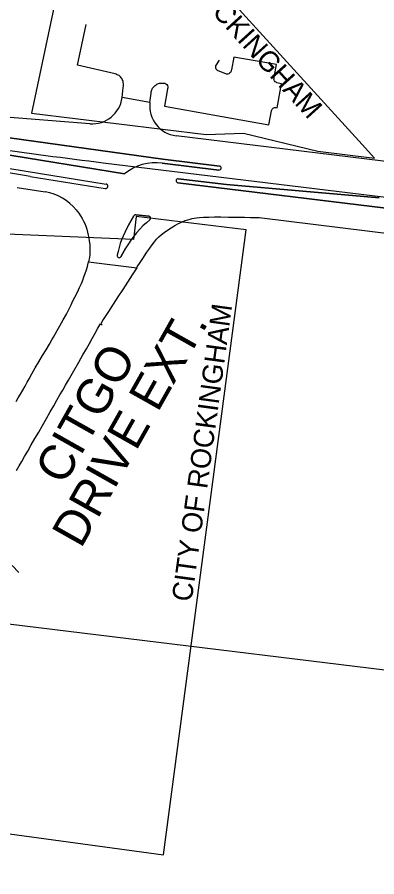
# Model space of a CAD drawing. Extents: x 1756435 to 1766932, y 416863 to 426859.
# Drawn here: x 1763464 to 1763823, y 423038 to 423897 of the extents above; entities that cross this region are included whole.
import ezdxf

# ---------------------------------------------------------------- set-up
doc = ezdxf.new("R2010")
doc.units = 0
for name, color, linetype in [('Exist Boundary City Limits', 7, 'Continuous'), ('Exist Roads EOP', 7, 'Continuous'), ('Exist Roads EOP Other', 7, 'Continuous'), ('Prop Horizontal Alignment', 7, 'Continuous'), ('Prop Lane Lines', 7, 'Continuous'), ('Prop Shade Light', 7, 'Continuous'), ('Prop Shade Medium', 7, 'Continuous'), ('Sheet Data Field CELL', 7, 'Continuous'), ('Sheet Plan CELL', 7, 'Continuous')]:
    doc.layers.add(name, color=color, linetype=linetype)

msp = doc.modelspace()

# ---------------------------------------------------------------- linework, layer by layer
at = {"layer": 'Exist Boundary City Limits'}
for points in [[(1763808.64, 423769.81), (1763627.49, 423968.89), (1763535.51, 424069.97), (1763478.5, 423801.07), (1763652.88, 423779.73), (1763689.95, 423781.03), (1763764.16, 423763.14), (1763820.91, 423756.2), (1763808.64, 423769.81), (1763808.64, 423769.81)], [(1762880.67, 423159.66), (1763610.22, 423060.06), (1763692.83, 423684.46), (1763583.09, 423697.89), (1763580.16, 423674.65), (1763153.55, 423692.65), (1763091.03, 423571.76), (1763039.83, 423506.29), (1762974.04, 423447.46), (1762934.14, 423389.22), (1762925.42, 423350.93), (1762898.59, 423287.45), (1762877.48, 423297.28), (1762869.53, 423205.69), (1762867.5, 423196.1), (1762876.5, 423188.61), (1762880.67, 423159.66)]]:
    msp.add_lwpolyline(points, dxfattribs=at)
at = {"layer": 'Exist Roads EOP'}
for points in [[(1763518.12, 423611.9), (1763518.87, 423611.48), (1763521.84, 423617.05), (1763524.4, 423622.2), (1763526.54, 423626.81), (1763528.25, 423630.76), (1763529.65, 423634.27), (1763530.88, 423637.53), (1763532.05, 423640.81), (1763533.26, 423644.38), (1763534.37, 423647.95), (1763535.22, 423651.25), (1763535.49, 423652.55)], [(1763583.56, 423646.67), (1763578.84, 423639.37), (1763574.19, 423632.11), (1763569.53, 423624.86), (1763564.79, 423617.53), (1763560.03, 423610.24), (1763555.25, 423602.9), (1763550.2, 423594.91), (1763547.56, 423590.63), (1763549.05, 423589.64)], [(1763463.21, 423513.11), (1763465.23, 423516.58), (1763467.46, 423520.39), (1763469.74, 423524.36), (1763472.02, 423528.41), (1763474.11, 423532.15), (1763476.13, 423535.72), (1763478.85, 423540.48), (1763482.31, 423546.49), (1763485.91, 423552.68), (1763489.54, 423558.84), (1763493.07, 423564.77), (1763496.37, 423570.27), (1763498.81, 423574.44), (1763500.42, 423577.35), (1763502.11, 423580.37), (1763504.1, 423583.87), (1763506.78, 423588.64), (1763510.1, 423594.57), (1763513.33, 423600.28), (1763516.23, 423605.45), (1763518.17, 423609.5), (1763518.75, 423611.08)], [(1763463.65, 423443.97), (1763466.31, 423448.61), (1763468.84, 423453.01), (1763471.68, 423457.98), (1763474.82, 423463.49), (1763478.29, 423469.56), (1763481.94, 423475.97), (1763485.68, 423482.51), (1763489.49, 423489.17), (1763493.37, 423495.96), (1763497.16, 423502.57), (1763500.66, 423508.7), (1763503.9, 423514.34), (1763506.85, 423519.51), (1763509.66, 423524.42), (1763512.47, 423529.32), (1763515.27, 423534.21), (1763518.07, 423539.08), (1763520.77, 423543.79), (1763525.61, 423552.25), (1763529.72, 423559.49), (1763533.28, 423565.72), (1763536.34, 423571.05), (1763539.09, 423575.94), (1763541.68, 423580.66), (1763544.81, 423586.34), (1763546.62, 423589.61), (1763547.37, 423590.42)], [(1763465.98, 423342.28), (1763459.18, 423349.28)]]:
    msp.add_lwpolyline(points, dxfattribs=at)
at = {"layer": 'Exist Roads EOP Other'}
for p, q in [((1763662.41, 423848.24), (1763666.03, 423853.79)), ((1763673.24, 423840.06), (1763664.15, 423843.46)), ((1763568.87, 423816.5), (1763570.15, 423826.52)), ((1763596.72, 423811.7), (1763597.84, 423821.11))]:
    msp.add_line(p, q, dxfattribs=at)
for points in [[(1763561.98, 423840.15), (1763524.39, 423848.86), (1763533, 423889.67)], [(1763720.86, 423836.83), (1763722.97, 423849.59), (1763680.54, 423856.96), (1763678.14, 423844.19)], [(1763722.21, 423806.74), (1763723.78, 423806.46), (1763727.88, 423830.19), (1763723.54, 423831.42)], [(1763614.32, 423825.15), (1763611.16, 423808.13), (1763659.36, 423799.42), (1763715.44, 423789.39), (1763718.07, 423803.32)]]:
    msp.add_lwpolyline(points, dxfattribs=at)
for points in [[(1763664.15, 423843.46), (1763662.89, 423844.88), (1763662.42, 423846.99), (1763662.41, 423848.24)], [(1763678.14, 423844.19), (1763676.97, 423841.63), (1763675.45, 423840.36), (1763673.24, 423840.06)], [(1763570.15, 423826.52), (1763570.16, 423831.68), (1763568.65, 423835.5), (1763565.88, 423838.45), (1763561.98, 423840.15)], [(1763723.54, 423831.42), (1763721.82, 423832.29), (1763720.51, 423834.47), (1763720.86, 423836.83)], [(1763597.84, 423821.11), (1763598.9, 423825.09), (1763601.33, 423828.06), (1763604.44, 423830.29), (1763608.53, 423831), (1763611.43, 423830.8), (1763613.61, 423829.58), (1763614.7, 423827.25), (1763614.32, 423825.15)], [(1763718.07, 423803.32), (1763718.78, 423805.03), (1763719.79, 423806.01), (1763722.21, 423806.74)]]:
    msp.add_spline(points, degree=3, dxfattribs=at)
at = {"layer": 'Prop Horizontal Alignment'}
msp.add_line((1763550.1, 423751.51), (1764163.47, 423676.45), dxfattribs=at)
msp.add_arc((1764278.89, 429707.08), 6000, 260.81671, 263.023399, dxfattribs=at)
at = {"layer": 'Prop Lane Lines'}
for p, q in [((1763178.83, 423790.71), (1763552.88, 423730.24)), ((1763477.32, 423737.89), (1763552.16, 423725.79))]:
    msp.add_line(p, q, dxfattribs=at)
for centre, radius, start, end in [((1763078.34, 421269.93), 2500, 80.8167, 83.0234), ((1763552.52, 423728.01), 2.25, 260.8167, 80.8167)]:
    msp.add_arc(centre, radius, start, end, dxfattribs=at)
at = {"layer": 'Prop Shade Light'}
for p, q in [((1763571.42, 423740.41), (1763135.37, 423810.9)), ((1763596.72, 423811.7), (1763568.87, 423816.5)), ((1763262.21, 423803.18), (1763609.64, 423755.05)), ((1763536.79, 423790.39), (1763337.9, 423805.82)), ((1764006.76, 423731.39), (1763622.87, 423778.37)), ((1763665.57, 423744.18), (1763608.88, 423751.11)), ((1763609.64, 423755.05), (1763666.06, 423748.15)), ((1763957.95, 423690.77), (1763624.49, 423731.57)), ((1763624.97, 423735.54), (1763673.15, 423729.65)), ((1763464.23, 423726.84), (1763492.16, 423722.32)), ((1763673.15, 423729.65), (1763825.39, 423716.31)), ((1763575.26, 423688.96), (1763580.7, 423698.51)), ((1763580.7, 423698.51), (1763575.26, 423688.96)), ((1763582.65, 423699.5), (1763595.66, 423698.14)), ((1763595.66, 423698.14), (1763582.65, 423699.5)), ((1763705.62, 423696.71), (1764159.15, 423641.21)), ((1763572.77, 423666.41), (1763567.78, 423657.65)), ((1763567.78, 423657.65), (1763572.77, 423666.41)), ((1763535.49, 423652.55), (1763583.56, 423646.67))]:
    msp.add_line(p, q, dxfattribs=at)
for points in [[(1763523.11, 423704.34), (1763523.99, 423703.26), (1763525.77, 423700.95), (1763527.48, 423698.51), (1763529.07, 423695.85), (1763530.49, 423693.15), (1763531.66, 423690.64), (1763532.69, 423688.05), (1763533.68, 423685.15), (1763534.53, 423682.15), (1763535.16, 423679.28), (1763535.68, 423676.31), (1763536.21, 423673), (1763536.62, 423669.85), (1763536.81, 423667.35), (1763536.84, 423665.02), (1763536.76, 423662.37), (1763536.57, 423659.61), (1763536.28, 423656.98), (1763535.85, 423654.26), (1763535.49, 423652.55)], [(1763583.56, 423646.67), (1763584.03, 423647.39), (1763586.85, 423651.73), (1763589.55, 423655.86), (1763593.73, 423662.21), (1763596.47, 423666.29), (1763598.88, 423669.64), (1763601.17, 423672.53), (1763603.38, 423675.07), (1763605.56, 423677.32), (1763608.06, 423679.59), (1763610.94, 423681.92), (1763614.24, 423684.24), (1763617.91, 423686.52), (1763621.65, 423688.72), (1763625.36, 423690.78), (1763628.84, 423692.44), (1763632.02, 423693.67), (1763634.69, 423694.58), (1763636.87, 423695.21), (1763638.91, 423695.75), (1763640.93, 423696.21), (1763643.26, 423696.56), (1763646.09, 423696.81), (1763650.15, 423697.03), (1763655.44, 423697.22), (1763661.18, 423697.31), (1763667.4, 423697.3), (1763675.03, 423697.22), (1763683.78, 423697.1), (1763691.05, 423696.98), (1763696.95, 423696.86), (1763704.58, 423696.73), (1763705.62, 423696.71)]]:
    msp.add_lwpolyline(points, dxfattribs=at)
for centre, radius, start, end in [((1763539.11, 423820.3), 30, 265.56344, 352.73451), ((1763626.51, 423808.14), 30, 173.20156, 263.0234), ((1763602.8, 423701.49), 50, 83.0234, 128.88147), ((1763665.81, 423746.16), 2, 263.0234, 83.0234), ((1763624.73, 423733.56), 2, 83.0234, 263.0234), ((1763484.18, 423672.96), 50, 38.86914, 80.8167), ((1763582.44, 423697.51), 2, 84.03555, 150.31774), ((1763582.44, 423697.51), 2, 84.03555, 150.31774), ((1763595.45, 423696.16), 2, 309.00381, 84.03555), ((1763595.45, 423696.16), 2, 309.00381, 84.03555), ((1763662.14, 423639.44), 100, 150.31774, 168.69893), ((1763662.14, 423639.44), 100, 150.31774, 168.69893), ((1763659.65, 423616.89), 100, 129.00381, 150.31774), ((1763659.65, 423616.89), 100, 129.00381, 150.31774), ((1763566.04, 423658.64), 2, 168.69893, 330.31774), ((1763566.04, 423658.64), 2, 168.69893, 330.31774)]:
    msp.add_arc(centre, radius, start, end, dxfattribs=at)
at = {"layer": 'Prop Shade Medium'}
for p, q in [((1763135.37, 423810.9), (1763571.42, 423740.41)), ((1763609.64, 423755.05), (1763262.21, 423803.18)), ((1763608.88, 423751.11), (1763665.57, 423744.18)), ((1763666.06, 423748.15), (1763609.64, 423755.05)), ((1763624.49, 423731.57), (1763957.95, 423690.77)), ((1763673.15, 423729.65), (1763624.97, 423735.54)), ((1763825.39, 423716.31), (1763673.15, 423729.65))]:
    msp.add_line(p, q, dxfattribs=at)
for centre, radius, start, end in [((1763602.8, 423701.49), 50, 83.0234, 128.88147), ((1763665.81, 423746.16), 2, 263.0234, 83.0234), ((1763624.73, 423733.56), 2, 83.0234, 263.0234)]:
    msp.add_arc(centre, radius, start, end, dxfattribs=at)
at = {"layer": 'Sheet Plan CELL'}
msp.add_lwpolyline([(1762817.94, 424426.51), (1764168.29, 424261.27), (1764040.75, 423219.04), (1762690.4, 423384.28)], dxfattribs=at)

# ---------------------------------------------------------------- texts
at = {"layer": 'Sheet Data Field CELL'}
for s, height, rotation, p in [('DRIVE EXT.', 35, 60.59245, (1763527.88, 423365.38)), ('CITGO', 35, 60.59245, (1763510.93, 423428.31)), ('THIS IS A PARTIAL CONTROLLED ACCESS PROJECT WITH ACCESS BEING LIMITED TO POINTS SHOWN ON THE PLANS.', 39.7496, 353.0234, (1760479.7, 423236.64))]:
    msp.add_text(s, height=height, rotation=rotation, dxfattribs=at).set_placement(p)
at = {"layer": 'Sheet Plan CELL'}
for rotation, p in [(312.17419, (1763554.33, 424015.91)), (82.22296, (1763638.34, 423312.32))]:
    msp.add_text('CITY OF ROCKINGHAM', height=20.16, rotation=rotation, dxfattribs=at).set_placement(p)

doc.saveas('drawing.dxf')
